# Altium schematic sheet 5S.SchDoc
size 431 x 279 mm; Date: Not shown in title block; ApprovedBy: Not shown in title block; CheckedBy: Not shown in title block; Author: Not shown in title block; CompanyName: Not shown in title block; Engineer: Not shown in title block; Organization: Not shown in title block; Address1: Not shown in title block; Address2: Not shown in title block; Address3: Not shown in title block; Address4: Not shown in title block; DocumentNumber: 3; Revision: Use project parameter SCH_Rev; SheetNumber: 3; SheetTotal: 5; PageSetup: Record=PageOptions¦CenterHorizontal=True¦CenterVertical=True¦PrintScale=0.64¦XCorrection=1.00¦YCorrection=1.00¦PrintKind=0¦BorderSize=5000000¦LeftOffset=0¦BottomOffset=0¦Orientation=2¦PaperLength=1000¦PaperWidth=1000¦Scale=100¦PaperSource=15¦PrintQuality=600¦MediaType=1¦DitherType=10¦PrintScaleMode=1¦PaperKind=Letter
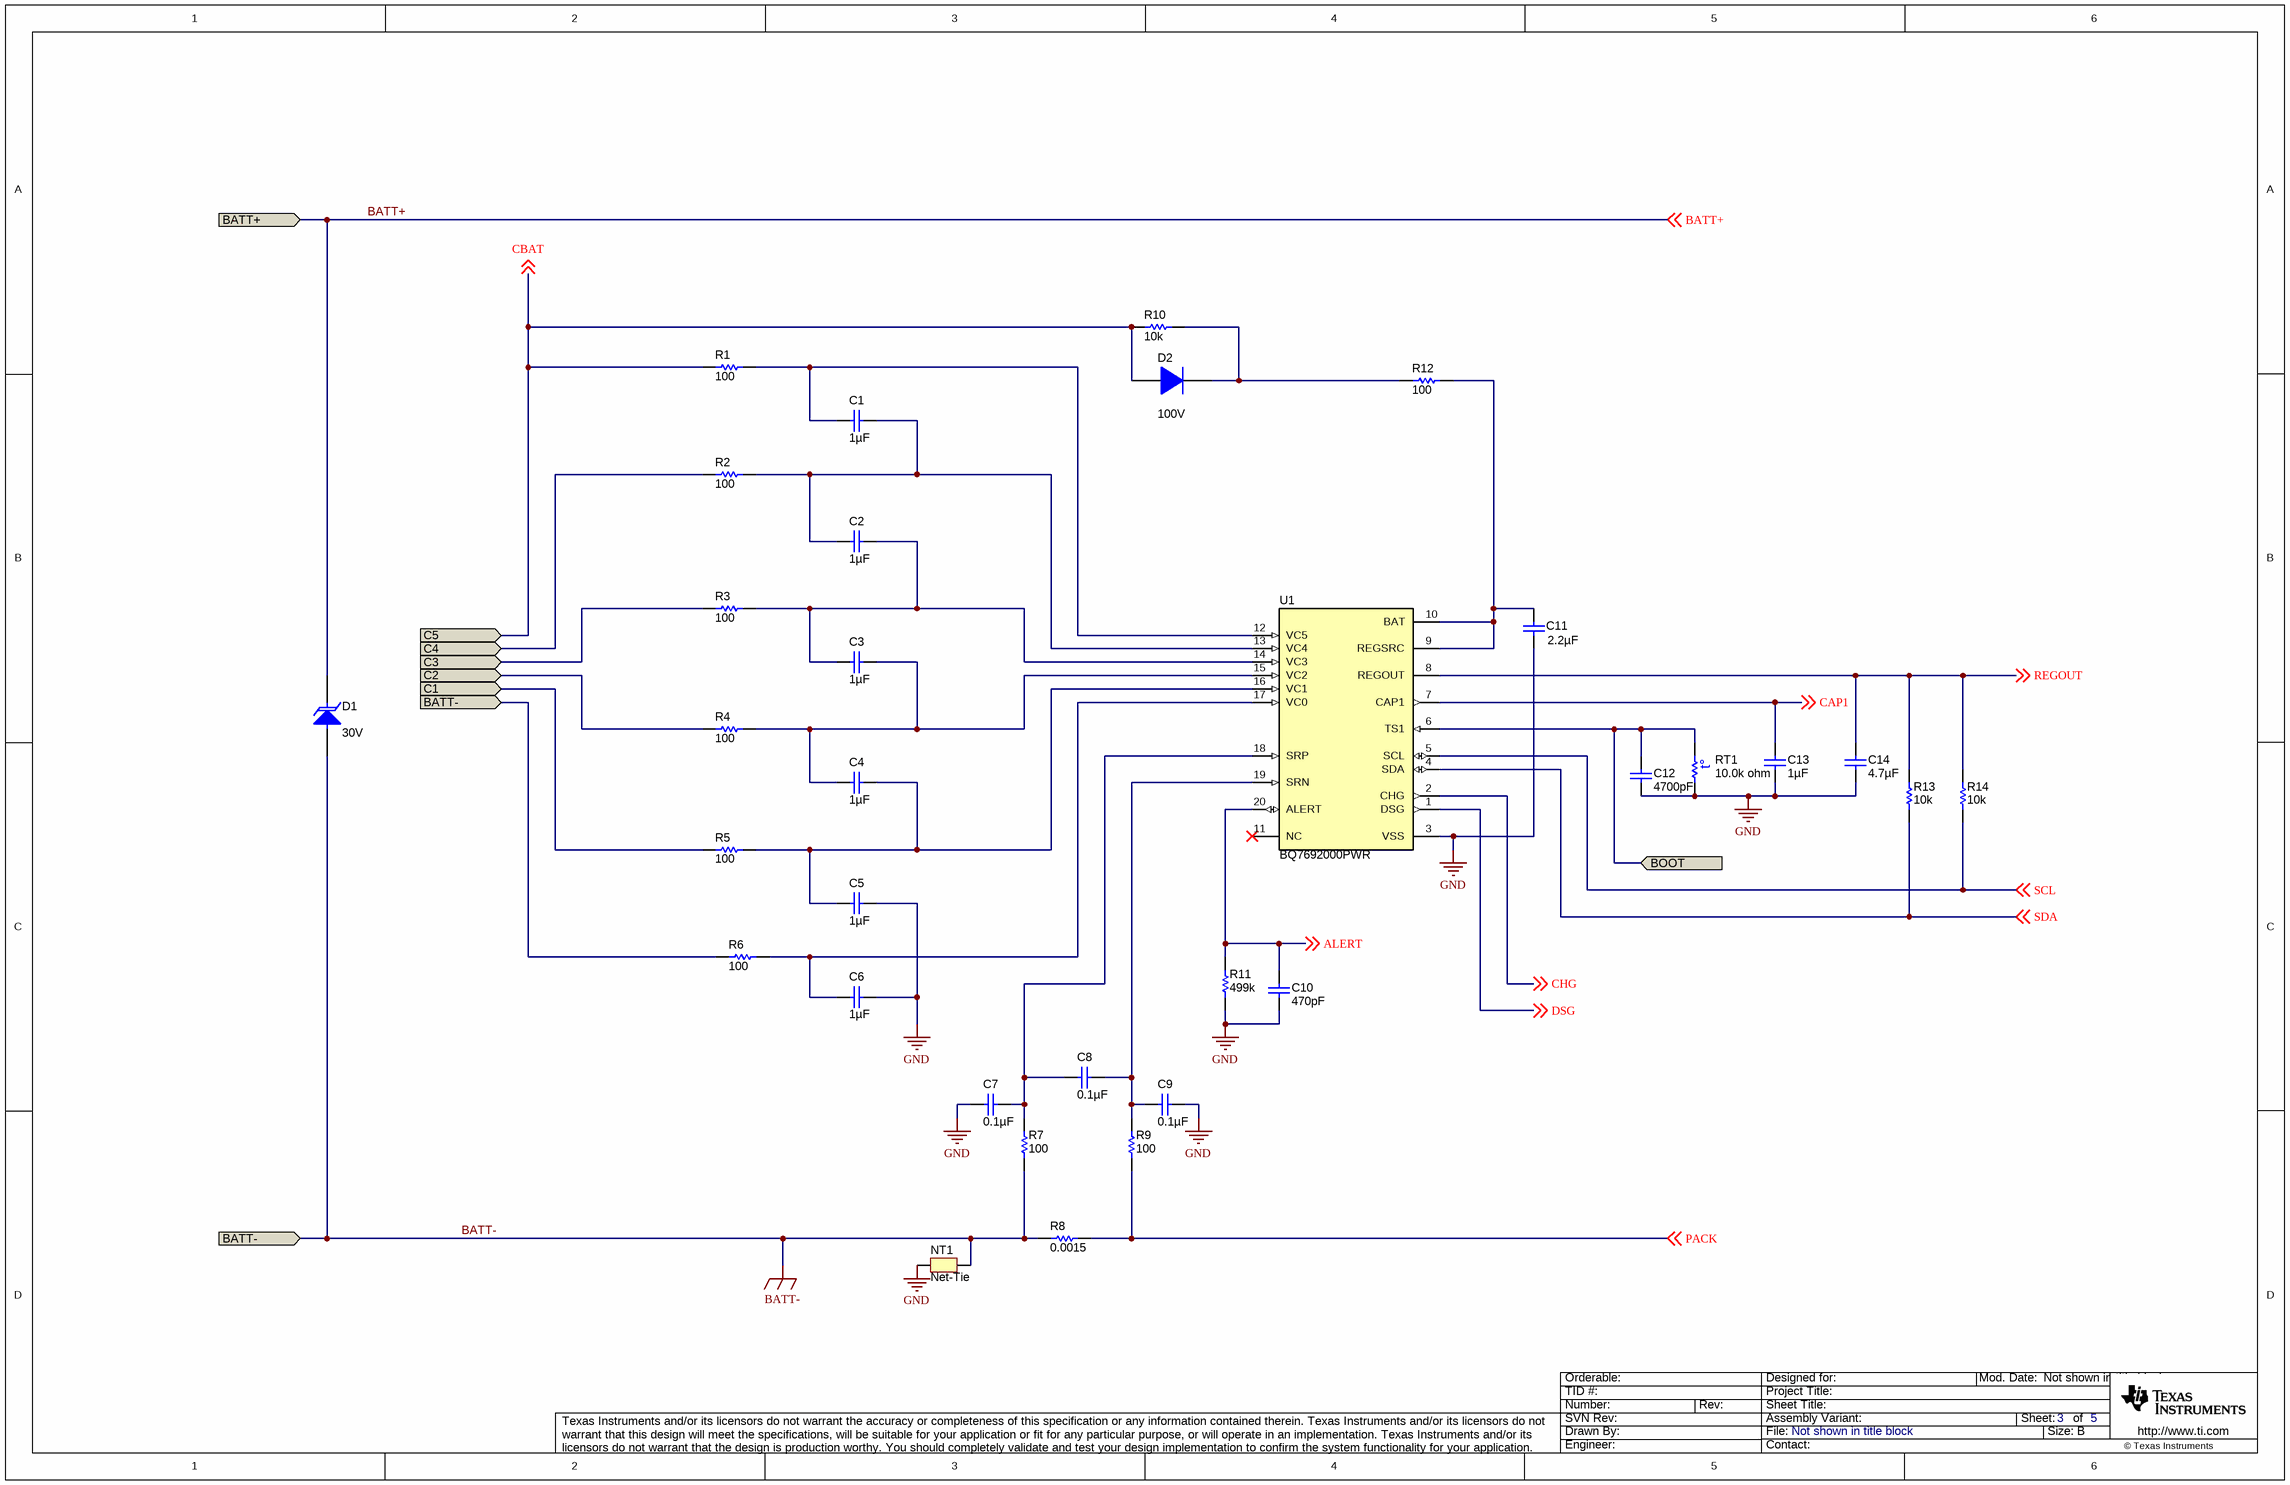
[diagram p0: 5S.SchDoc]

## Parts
C1  ValueDisplayed: 1µF  [0805_HV]  (hidden comment: GRM21BR71C105KA01L)
C2  ValueDisplayed: 1µF  [0805_HV]  (hidden comment: GRM21BR71C105KA01L)
C3  ValueDisplayed: 1µF  [0805_HV]  (hidden comment: GRM21BR71C105KA01L)
C4  ValueDisplayed: 1µF  [0805_HV]  (hidden comment: GRM21BR71C105KA01L)
C5  ValueDisplayed: 1µF  [0805_HV]  (hidden comment: GRM21BR71C105KA01L)
C6  ValueDisplayed: 1µF  [0805_HV]  (hidden comment: GRM21BR71C105KA01L)
C7  ValueDisplayed: 0.1µF  [0603_095]  (hidden comment: 885012206095)
C8  ValueDisplayed: 0.1µF  [0603_095]  (hidden comment: 885012206095)
C9  ValueDisplayed: 0.1µF  [0603_095]  (hidden comment: 885012206095)
C10  ValueDisplayed: 470pF  [0603_095]  (hidden comment: 885012206081)
C11  ValueDisplayed: 2.2µF  [1206_180]  (hidden comment: GRM31CR61H225KA88L)
C12  ValueDisplayed: 4700pF  [0603_095]  (hidden comment: 885012206087)
C13  ValueDisplayed: 1µF  [0603_095]  (hidden comment: 885012206052)
C14  ValueDisplayed: 4.7µF  [0805_145]  (hidden comment: 885012207025)
D1  value 30V  [SMC]  (hidden comment: SMCJ30A)
D2  value 100V  [SOD-123]  (hidden comment: 1N4148W-7-F)
NT1  Net-Tie  [Net-Tie_10mil]  (net tie, no BOM)
R1  ValueDisplayed: 100  [1206]  (hidden comment: CRCW1206100RFKEA)
R2  ValueDisplayed: 100  [1206]  (hidden comment: CRCW1206100RFKEA)
R3  ValueDisplayed: 100  [1206]  (hidden comment: CRCW1206100RFKEA)
R4  ValueDisplayed: 100  [1206]  (hidden comment: CRCW1206100RFKEA)
R5  ValueDisplayed: 100  [1206]  (hidden comment: CRCW1206100RFKEA)
R6  ValueDisplayed: 100  [1206]  (hidden comment: CRCW1206100RFKEA)
R7  value 100  [0805_HV]  (hidden comment: CRCW0805100RFKEA)
R8  ValueDisplayed: 0.0015  [ULRB22512_085]  (hidden comment: ULRB22512R0015FLFSLT)
R9  value 100  [0805_HV]  (hidden comment: CRCW0805100RFKEA)
R10  ValueDisplayed: 10k  [0603]  (hidden comment: CRCW060310K0JNEA)
R11  ValueDisplayed: 499k  [0603]  (hidden comment: CRCW0603499KFKEA)
R12  ValueDisplayed: 100  [1206]  (hidden comment: CRCW1206100RFKEA)
R13  ValueDisplayed: 10k  [0603]  (hidden comment: CRCW060310K0JNEA)
R14  ValueDisplayed: 10k  [0603]  (hidden comment: CRCW060310K0JNEA)
RT1  value 10.0k ohm  [Thermistor_103AT-2]  (hidden comment: 103AT-2)
U1  BQ7692000PWR  [PW0020A_N]

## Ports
BATT+, BATT-, BOOT, C1, C2, C3, C4, C5

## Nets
BATT-: D1.2(A) NT1.2 R6.1 R7.1 R8.1 ; port BATT-
GND: C5.1 C6.1 C7.2 C9.1 C10.2 C11.2 C12.2 C13.2 C14.2 NT1.1 R11.1 RT1.1 U1.3(VSS)
ALERT: C10.1 R11.2 U1.20(ALERT) ; off-sheet ALERT
BATT+: D1.1(K) ; off-sheet BATT+, port BATT+
BOOT: C12.1 RT1.2 U1.6(TS1) ; port BOOT
C1: R5.1 ; port C1
C2: R4.1 ; port C2
C3: R3.1 ; port C3
C4: R2.1 ; port C4
CAP1: C13.1 U1.7(CAP1) ; off-sheet CAP1
CBAT: D2.2(A) R1.1 R10.1 ; off-sheet CBAT, port C5
CHG: U1.2(CHG) ; off-sheet CHG
DSG: U1.1(DSG) ; off-sheet DSG
PACK: R8.2 R9.1 ; off-sheet PACK
REGOUT: C14.1 R13.2 R14.1 U1.8(REGOUT) ; off-sheet REGOUT
SCL: R14.2 U1.5(SCL) ; off-sheet SCL
SDA: R13.1 U1.4(SDA) ; off-sheet SDA
NetC1_1: C1.1 C2.2 R2.2 U1.13(VC4)
NetC1_2: C1.2 R1.2 U1.12(VC5)
NetC2_1: C2.1 C3.2 R3.2 U1.14(VC3)
NetC3_1: C3.1 C4.2 R4.2 U1.15(VC2)
NetC4_1: C4.1 C5.2 R5.2 U1.16(VC1)
NetC6_2: C6.2 R6.2 U1.17(VC0)
NetC7_1: C7.1 C8.2 R7.2 U1.18(SRP)
NetC8_1: C8.1 C9.2 R9.2 U1.19(SRN)
NetC11_1: C11.1 R12.2 U1.9(REGSRC) U1.10(BAT)
NetD2_1: D2.1(K) R10.2 R12.1

Not connected (* = marked no-connect by the designer): U1 11(NC)*

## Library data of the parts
C1-C6 = GRM21BR71C105KA01L: CAP, CERM, 1 µF, 16 V, +/- 10%, X7R, 0805; Manufacturer: MuRata; Polarized: N; CompType: Capacitor; Value: 1uF; U/M: EA; Cap_F: 0.000001; Tolerance_%: 10; ESR_ohm: 0.003; Value1: 0.003 ohm; VDC_V: 16; Value2: 16V; TaMin_C: -55; TaMax_C: 125; Cap_Case: 0805; SizeArea_mm2: 2.5; SizeAreaWB_mm2: 6.75; SizeX_mm: 2; SizeY_mm: 1.25; SizeZ_mm: 1.45; AEC Category: Q200
C7-C9 = 885012206095: CAP, CERM, 0.1 µF, 50 V, +/- 10%, X7R, 0603_095; Manufacturer: Wurth Elektronik; Polarized: N; CompType: Capacitor; Value: 0.1uF; U/M: EA; Cap_F: 0.0000001; Tolerance_%: 10; Value1: Unknown; VDC_V: 50; Value2: 50V; TaMin_C: -55; TaMax_C: 125; Cap_Case: 0603
C10 = 885012206081: CAP, CERM, 470 pF, 50 V, +/- 10%, X7R, 0603_095; Manufacturer: Wurth Elektronik; Polarized: N; CompType: Capacitor; Value: 470pF; U/M: EA; Cap_F: 0.00000000047; Tolerance_%: 10; Value1: Unknown; VDC_V: 50; Value2: 50V; TaMin_C: -55; TaMax_C: 125; Cap_Case: 0603
C11 = GRM31CR61H225KA88L: CAP, CERM, 2.2 µF, 50 V, +/- 10%, X5R, 1206; Manufacturer: MuRata; Polarized: N; CompType: Capacitor; Value: 2.2uF; U/M: EA; Cap_F: 0.0000022; Tolerance_%: 10; Value1: Unknown; VDC_V: 50; Value2: 50V; TaMin_C: -55; TaMax_C: 85; Cap_Case: 1206; SizeArea_mm2: 5.12; SizeAreaWB_mm2: 10.92; SizeX_mm: 3.2; SizeY_mm: 1.6; SizeZ_mm: 1.8; AEC Category: Q200
C12 = 885012206087: CAP, CERM, 4700 pF, 50 V, +/- 10%, X7R, 0603_095; Manufacturer: Wurth Elektronik; Polarized: N; CompType: Capacitor; Value: 4700pF; U/M: EA; Cap_F: 0.0000000047; Tolerance_%: 10; Value1: Unknown; VDC_V: 50; Value2: 50V; TaMin_C: -55; TaMax_C: 125; Cap_Case: 0603
C13 = 885012206052: CAP, CERM, 1 µF, 16 V, +/- 10%, X7R, 0603_095; Manufacturer: Wurth Elektronik; Polarized: N; CompType: Capacitor; Value: 1uF; U/M: EA; Cap_F: 0.000001; Tolerance_%: 10; Value1: Unknown; VDC_V: 16; Value2: 16V; TaMin_C: -55; TaMax_C: 125; Cap_Case: 0603
C14 = 885012207025: CAP, CERM, 4.7 µF, 10 V, +/- 10%, X7R, 0805; Manufacturer: Wurth Elektronik; Polarized: N; CompType: Capacitor; Value: 4.7uF; U/M: EA; Cap_F: 0.0000047; Tolerance_%: 10; Value1: Unknown; Value2: 10V; TaMin_C: -55; TaMax_C: 125; Cap_Case: 0805
D1 = SMCJ30A: Diode, TVS, Uni, 30 V, SMC; Manufacturer: Fairchild Semiconductor; U/M: EA; Vr_V: 30; Value1: W; SizeAreaWB_mm2: 83.2686; SizeArea_mm2: 50.5686; SizeX_mm: 8.13; SizeY_mm: 6.22; SizeZ_mm: 2.6; AEC Category: Q101
D2 = 1N4148W-7-F: Diode, Ultrafast, 100V, 0.15A, SOD-123; Manufacturer: Diodes Inc.; U/M: EA; Vf_V: 1.25; Value2: 1.25V; Io_A: 0.15; Vr_V: 100; TJmax_C: 150
NT1 = Net-Tie: Single point connection between nets.; SymbolCreator: codlsc
R1-R6 R12 = CRCW1206100RFKEA: RES, 100, 1%, 0.25 W, 1206; Manufacturer: Vishay-Dale; CompType: Resistor; Value: 100; Value_Code: 100R; Tolerance_%: 1; Power_W: 0.25; Value2: 0.25W; VDC_V: 200; TempCo: 100 ppm/C; SizeArea_mm2: 5.12; SizeX_mm: 3.2; SizeY_mm: 1.6; SizeZ_mm: 1.35; EIA_Code: E96; U/M: EA; AEC Category: Q200
R7 R9 = CRCW0805100RFKEA: RES, 100 ohm, 1%, 0.125W, 0805; Manufacturer: Vishay-Dale; CompType: Resistor; Value_Code: 100R; Tolerance_%: 1; Power_W: 0.125; VDC_V: 150; TempCo: 100 ppm/C; EIA_Code: E96; U/M: EA
R8 = ULRB22512R0015FLFSLT: RES, 0.0015, 1%, 2 W, AEC-Q200 Grade 0, 2512; Manufacturer: TT Electronics/IRC; CompType: Resistor; Value: 0.0015; Value_Code: 1L500; Tolerance_%: 1; Power_W: 2; Value2: 2W; TempCo: 50 ppm/C; U/M: EA; AEC Category: Q200; AEC Qualified: Y; AEC Grade: 0
R10 R13 R14 = CRCW060310K0JNEA: RES, 10 k, 5%, 0.1 W, 0603; Manufacturer: Vishay-Dale; CompType: Resistor; Value: 10k; Res_ohm: 10000; Value_Code: 10k0; Tolerance_%: 5; Power_W: 0.1; Value2: 0.1W; VDC_V: 75; TempCo: 200 ppm/C; EIA_Code: E24; U/M: EA
R11 = CRCW0603499KFKEA: RES, 499 k, 1%, 0.1 W, 0603; Manufacturer: Vishay-Dale; CompType: Resistor; Value: 499k; Res_ohm: 499000; Tolerance_%: 1; Power_W: 0.1; Value2: 0.1W; VDC_V: 75; TempCo: 100 ppm/C; EIA_Code: E96; U/M: EA
RT1 = 103at-2: Thermistor NTC, 10.0k ohm, 1%, Disc, 5x8.4 mm; Manufacturer: SEMITEC Corporation; Tolerance_%: 1; Power_W: 0.01; TaMin_C: -50; TaMax_C: 110; U/M: EA
U1 = BQ7692000PWR: Battery Monitor for Lithium-Ion and Phosphate Battery Packs, PW0020A (TSSOP-20); Manufacturer: Texas Instruments; SymbolCreator: a0411947; SizeArea_mm2: 43.56; SizeAreaWB_mm2: 73.96; SizeX_mm: 6.6; SizeZ_mm: 1.2; CompType: IC; U/M: EA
